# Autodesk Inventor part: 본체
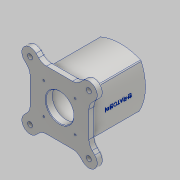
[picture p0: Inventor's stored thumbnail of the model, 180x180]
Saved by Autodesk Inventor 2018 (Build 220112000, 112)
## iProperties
Created: 2022-01
Part Number: 본체
Material: 알루미늄 6061
Document SubType Name: Modeling
Designer: home
Density: 2.7 g/cm^3
Appearance: 알루미늄 - 평지
Mass: 1226.53 g
Surface Area: 908.487 cm^2
Volume: 454.27 cm^3
Author: home
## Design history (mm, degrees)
sketch "스케치1"
  geometry: L1 (32.942, -45)-(-32.942, -45); L2 (45, -45)-(-45, 45); L3 (-45, -45)-(45, 45); L4 (0, 0)-(0, -55.815); A1 r 90 centre (-45, 0) between (32.942, -45) and (37.029, 37.029); A2 r 90 centre (45, 0) between (-37.029, 37.029) and (-32.942, -45); A3 r 90 centre (0, -45) between (37.029, 37.029) and (-37.029, 37.029); 2 further points
  constraints: 8 end point, 7 point on circle, 3 centre point, 3 symmetric about line, 2 point on line, 1 equal radius, 1 horizontal, 1 midpoint, 1 perpendicular, 1 vertical, 1 other
  dimensions: "d2" = 90 distance of L2.end L3.end; "d3" = 90 distance of L3.start L2.end; "d4" = 180 diameter of A1; "d5" = 135 deg angle of L2 L4; "d6" = 0 distance from line of L4.start L2; "d7" = 0 distance from line of L4.start L3; "d8" = 45 distance from line of L4.start L1; "d9" = 63.63961 distance from line of L3.end L2; "d10" = 63.63961 distance from line of L2.start L3; "d11" = 55.11352 distance from line of point (32.942, 45) L2; "d12" = 8.52609 distance from line of point (32.942, 45) L3; "d13" = 39.4673 distance from line of L4.end L2
extrude "돌출1" new body sketch "스케치1" stored distance "d14" = 110; taper "d15" = 0 deg
sketch "스케치2"
  geometry: L1 (0, 0)-(0, -106.241); L2 (0, 0)-(85.273, -85.273); L3 (42.426, -63.64)-(31.787, -53); L4 (-31.787, 53)-(31.787, 53); L5 (53, 31.787)-(53, -31.787); L6 (-53, -31.787)-(-53, 31.787); L7 (-53, 53)-(53, -53); L8 (53, 53)-(-53, -53); L9 (31.787, -53)-(-31.787, -53); L10 (63.64, -42.426)-(53, -31.787); L11 (42.426, 63.64)-(31.787, 53); L12 (63.64, 42.426)-(53, 31.787); L13 (-63.64, 42.426)-(-53, 31.787); L14 (-42.426, 63.64)-(-31.787, 53); L15 (-42.426, -63.64)-(-31.787, -53); L16 (-63.64, -42.426)-(-53, -31.787); L17 (-32.942, -45)-(32.942, -45) reference; A1 r 75 centre (0, 0) between (53.033, -53.033) and (41.355, -62.568); A2 r 15 centre (53.033, -53.033) between (41.419, -62.526) and (62.526, -41.419); A3 r 15 centre (53.033, 53.033) between (62.526, 41.419) and (41.419, 62.526); A4 r 15 centre (-53.033, 53.033) between (-41.419, 62.526) and (-62.526, 41.419); A5 r 15 centre (-53.033, -53.033) between (-62.526, -41.419) and (-41.419, -62.526); A6 r 90 centre (-45, 0) between (32.942, -45) and (37.029, 37.029) reference; A7 r 90 centre (0, -45) between (37.029, 37.029) and (-37.029, 37.029) reference; A8 r 90 centre (45, 0) between (-37.029, 37.029) and (-32.942, -45) reference; 10 further points
  constraints: 32 end point, 20 point on circle, 9 point on line, 9 tangent, 6 parallel, 5 centre point, 2 midpoint, 2 perpendicular, 2 symmetric about line, 1 coincident, 1 equal radius, 1 horizontal, 1 vertical
  dimensions: "d39" = 150 diameter of A1; "d40" = 45 deg angle of L2 L1; "d41" = 30 diameter of A2; "d42" = 15 distance between parallel lines of L2 L3; "d44" = 106 distance of L8.start L7.end; "d45" = 53 distance from line of L5 point (0, 0); "d46" = 106 distance between parallel lines of L6 L5; "d47" = 53 distance from line of point (0, 0) L9; "d48" = 42.87983 distance from line of point (95.88, -74.667) L5; "d49" = 32.27323 distance from line of L2.end L5; "d50" = 90.12402 distance from line of L1.end L10; "d54" = 53 distance from line of point (0, 0) L4; "d55" = 90 deg angle of L12 L10; "d56" = 90 deg angle of L16 L10; "d57" = 90 deg angle of L12 L7; "d58" = 15 distance between parallel lines of L8 L11; "d59" = 15 distance from line of point (0, 0) L12; "d60" = 15 distance from line of point (0, 0) L16; "d61" = 0 distance from line of point (95.88, -74.667) L10; "d62" = 60 distance from line of L12.start L10; "d63" = 58.48469 distance from line of point (62.568, 41.355) L10; "d64" = 58.5 distance from line of A3.start L10; "d65" = 59.95332 distance from line of L8.start L10; "d66" = 58.5 distance from line of A3.end L10; "d67" = 58.48469 distance from line of point (41.355, 62.568) L10; "d68" = 88.48469 distance from line of point (-41.355, 62.568) L12; "d69" = 88.48469 distance from line of point (-41.355, -62.568) L10; "d70" = 0.07519 distance from line of A4.start L10; "d71" = 88.5 distance from line of A4.start L12; "d72" = 88.5 distance from line of A5.end L10; "d73" = 0.07519 distance from line of A5.end L12; "d74" = 89.95332 distance from line of L7.start L12; "d75" = 89.95332 distance from line of L8.end L10; "d76" = 29.92481 distance from line of A4.end L10; "d77" = 88.5 distance from line of A5.start L10; "d78" = 88.48469 distance from line of point (-62.568, 41.355) L12; "d79" = 88.48469 distance from line of point (-62.568, -41.355) L10
extrude "돌출2" join sketch "스케치2" distance "d80" = 12; taper "d81" = 0 deg
sketch "스케치3"
  geometry: C1 r 25 at (0, 0); 1 further point
  constraints: 1 centre point, 1 coincident
  dimensions: "d82" = 50 diameter of C1
extrude "돌출3" cut sketch "스케치3" distance "d83" = 12; taper "d84" = 0 deg
sketch "스케치4"
  geometry: C1 r 37 at (0, 0); 1 further point
  constraints: 1 centre point, 1 coincident
  dimensions: "d85" = 74 diameter of C1
extrude "돌출4" cut sketch "스케치4" distance "d86" = 86; taper "d87" = 0 deg
sketch "스케치5"
  geometry: C1 r 25 at (0, 0); 1 further point
  constraints: 1 centre point, 1 coincident
  dimensions: "d88" = 50 diameter of C1
extrude "돌출5" cut sketch "스케치5" distance "d89" = 12; taper "d90" = 0 deg
node "작업 평면1"
sketch "스케치6"
  geometry: L1 (-31.787, -55)-(31.787, -55) reference; C1 r 20 at (0, 6); 1 further point
  constraints: 1 centre point, 1 vertical alignment
  dimensions: "d92" = 40 diameter of C1; "d93" = 61 distance from line of C1.centre L1
extrude "돌출6" join sketch "스케치6" distance "d94" = 12; taper "d95" = 10 deg
sketch "스케치7"
  geometry: C1 r 20 at (0, 0) reference; C2 r 12 at (0, 0); 1 further point
  constraints: 1 centre point, 1 coincident
  dimensions: "d96" = 24 diameter of C2
extrude "돌출7" cut sketch "스케치7" distance "d97" = 13; taper "d98" = 0 deg
sketch "스케치8"
  geometry: C1 r 12 at (0, 0) reference; C2 r 15 at (0, 0); 1 further point
  constraints: 1 centre point, 1 coincident
  dimensions: "d99" = 30 diameter of C2
extrude "돌출8" cut sketch "스케치8" distance "d100" = 13; taper "d101" = 0 deg
sketch "스케치9"
  geometry: L1 (31.787, 53)-(42.426, 63.64) reference; L2 (63.64, 42.426)-(53, 31.787) reference; L3 (53, 31.787)-(53, -31.787) reference; L4 (53, -31.787)-(63.64, -42.426) reference; L5 (42.426, -63.64)-(31.787, -53) reference; L6 (31.787, -53)-(-31.787, -53) reference; L7 (-31.787, -53)-(-42.426, -63.64) reference; L8 (-63.64, -42.426)-(-53, -31.787) reference; L9 (-53, -31.787)-(-53, 31.787) reference; L10 (-53, 31.787)-(-63.64, 42.426) reference; L11 (-42.426, 63.64)-(-31.787, 53) reference; L12 (-31.787, 53)-(31.787, 53) reference; C1 r 25 at (0, 0) reference; C2 r 9 at (-53.033, 53.033); C3 r 9 at (-53.033, -53.033); C4 r 9 at (53.033, -53.033); C5 r 9 at (53.033, 53.033); A1 r 15 centre (53.033, 53.033) between (63.64, 42.426) and (42.426, 63.64) reference; A2 r 15 centre (53.033, -53.033) between (42.426, -63.64) and (63.64, -42.426) reference; A3 r 15 centre (-53.033, -53.033) between (-63.64, -42.426) and (-42.426, -63.64) reference; A4 r 15 centre (-53.033, 53.033) between (-42.426, 63.64) and (-63.64, 42.426) reference; 1 further point
  constraints: 4 centre point, 3 concentric, 3 equal radius, 1 coincident
  dimensions: "d102" = 18 diameter of C2
extrude "돌출9" cut sketch "스케치9" distance "d106" = 2; taper "d107" = 0 deg
sketch "스케치10"
  geometry: L1 (-21.246, -0.033)-(-10.607, 10.607) reference; L2 (10.607, -10.607)-(-0.033, -21.246) reference; L3 (-0.033, -21.246)-(-0.033, -84.82) reference; L4 (-0.033, -84.82)-(10.607, -95.459) reference; L5 (-10.607, -116.673)-(-21.246, -106.033) reference; L6 (-21.246, -106.033)-(-84.82, -106.033) reference; L7 (-84.82, -106.033)-(-95.459, -116.673) reference; L8 (-116.673, -95.459)-(-106.033, -84.82) reference; L9 (-106.033, -84.82)-(-106.033, -21.246) reference; L10 (-106.033, -21.246)-(-116.673, -10.607) reference; L11 (-95.459, 10.607)-(-84.82, -0.033) reference; L12 (-84.82, -0.033)-(-21.246, -0.033) reference; C1 r 25 at (-53.033, -53.033) reference; C2 r 4.5 at (-106.066, 0); C3 r 4.5 at (-106.066, -106.066); C4 r 4.5 at (0, -106.066); C5 r 4.5 at (0, 0); A1 r 15 centre (0, 0) between (10.607, -10.607) and (-10.607, 10.607) reference; A2 r 15 centre (0, -106.066) between (-10.607, -116.673) and (10.607, -95.459) reference; A3 r 15 centre (-106.066, -106.066) between (-116.673, -95.459) and (-95.459, -116.673) reference; A4 r 15 centre (-106.066, 0) between (-95.459, 10.607) and (-116.673, -10.607) reference; 1 further point
  constraints: 4 centre point, 3 concentric, 3 equal radius, 1 coincident
  dimensions: "d108" = 9 diameter of C2
extrude "돌출10" cut sketch "스케치10" distance "d112" = 10; taper "d113" = 0 deg
sketch "스케치11" dims "d114" = 80
  geometry: L1 (0, 0)-(0, 66.966); L2 (0, 0)-(-28.284, 28.284); 1 further point
  constraints: 4 end point, 1 coincident, 1 vertical, 3 other
  dimensions: "d115" = 45 deg angle of L1 L2; "d149" = 47.35185 distance from line of L1.end L2
hole "구멍1" sketch "스케치11" at (-28.284, 28.284) diameter "d116" = 3.242; stored, may be unused: countersink angle "d120" = 90 deg, drill point angle "d122" = 118 deg; dims "d117" = 9, "d118" = 4, "d119" = 2, "d121" = 11
sketch "스케치12" dims "d126" = 80
  geometry: L1 (0, 0)-(-28.284, 28.284); L2 (0, 0)-(0, 64.675); 1 further point
  constraints: 4 end point, 1 coincident, 1 vertical, 3 other
  dimensions: "d127" = 45 deg angle of L2 L1; "d150" = 45.73242 distance from line of L2.end L1
hole "구멍2" sketch "스케치12" at (-28.284, 28.284) diameter "d128" = 3.242; stored, may be unused: countersink angle "d132" = 90 deg, drill point angle "d134" = 118 deg; dims "d129" = 9, "d130" = 4, "d131" = 2, "d133" = 11
fillet "모깎기1" dims "d138" = 20
fillet "모깎기2" dims "d139" = 3
fillet "모깎기3" dims "d140" = 3
chamfer "모따기1" distance "d141" = 1; stored, may be unused: second distance "d142" = 2, angle "d143" = 45 deg
node "작업 평면2"
sketch "스케치13"
  geometry: L1 (-55, -23.503)-(-55, 23.503) reference; L2 (-14, -55)-(26, -55) reference; 2 further points
  constraints: 1 other
  dimensions: "d145" = 61 distance from line of point (6, 0) L1; "d146" = 55 distance from line of point (6, 0) L2
feature "엠보싱1" sketch "스케치13" dims "d39" = 150, "d40" = 45 deg, "d41" = 30, "d42" = 15, "d44" = 106, "d45" = 53, "d46" = 106, "d47" = 53, "d48" = 42.87983, "d49" = 32.27323, "d50" = 90.12402, "d54" = 53, "d55" = 90 deg, "d56" = 90 deg, "d57" = 90 deg, "d58" = 15, "d59" = 15, "d60" = 15, "d61" = 0 deg, "d62" = 60, "d63" = 58.48469, "d64" = 58.5, "d65" = 59.95332, "d66" = 58.5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
node "솔리드1"
pattern_circular "원형 패턴1" dims angle "d124" = 360 deg
pattern_circular "원형 패턴2" dims angle "d136" = 360 deg
node "투영된 루프1"
node "투영된 루프2"
node "투영된 루프3"
node "투영된 루프4"
node "투영된 루프5"
other parameters: "d91" = -55, "d144" = 45
